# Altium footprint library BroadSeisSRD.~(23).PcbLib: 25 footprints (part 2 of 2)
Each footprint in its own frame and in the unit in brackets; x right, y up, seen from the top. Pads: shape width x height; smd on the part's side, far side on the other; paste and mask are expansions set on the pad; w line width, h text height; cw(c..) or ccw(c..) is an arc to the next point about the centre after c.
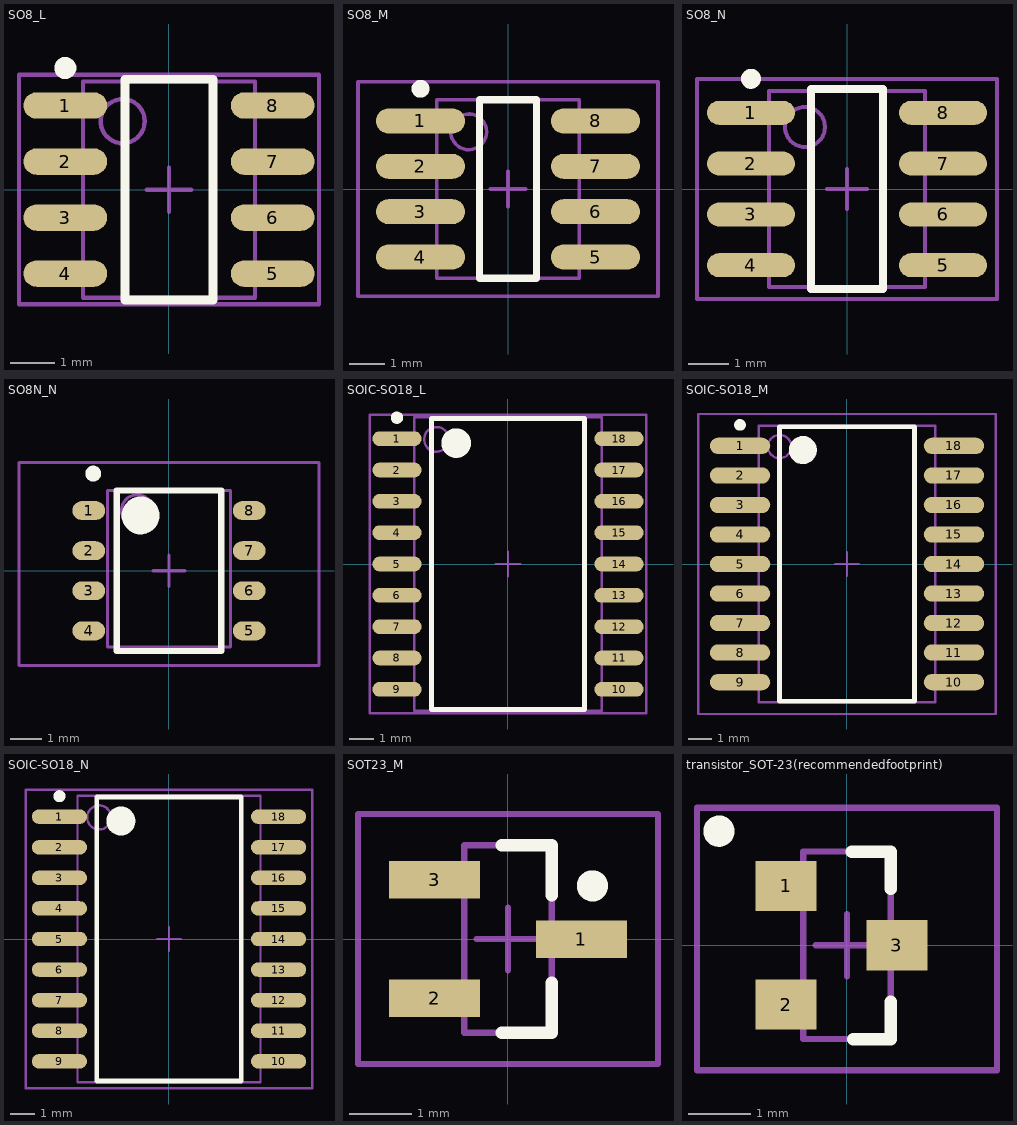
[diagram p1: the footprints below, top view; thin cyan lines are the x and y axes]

## SO8_L [mm] "SOIC, 8-Leads, Body 4.9x3.9mm, Pitch 1.27mm, IPC High Density"
height 1.75
pads (8):
  oval 1.9x0.6 smd: 1(-2.35,1.905) 2(-2.35,0.635) 3(-2.35,-0.635) 4(-2.35,-1.905) 5(2.35,-1.905) 6(2.35,-0.635) 7(2.35,0.635) 8(2.35,1.905)
Top Overlay:
  circle w0.25: c-2.35,2.755 r0.125
  lines w0.2: -1,-2.5 -1,2.5 1,2.5 1,-2.5 -1,-2.5
Mechanical 13:
  circle w0.1: c-1.05,1.55 r0.5
  lines w0.1: -1.95,-2.45 -1.95,2.45 1.95,2.45 1.95,-2.45 -1.95,-2.45
Mechanical 15:
  lines w0.1: -0.5,0 0.5,0 ; 0,-0.5 0,0.5 ; -3.4,-2.6 -3.4,2.6 3.4,2.6 3.4,-2.6 -3.4,-2.6
3D body: height 1.75, standoff 0, extent -1.95,-2.45 1.95,2.45

## SO8_M [mm] "SOIC, 8-Leads, Body 4.9x3.9mm, Pitch 1.27mm, IPC Low Density"
height 1.75
pads (8):
  oval 2.5x0.7 smd: 1(-2.45,1.905) 2(-2.45,0.635) 3(-2.45,-0.635) 4(-2.45,-1.905) 5(2.45,-1.905) 6(2.45,-0.635) 7(2.45,0.635) 8(2.45,1.905)
Top Overlay:
  circle w0.25: c-2.45,2.805 r0.125
  lines w0.2: -0.8,-2.5 -0.8,2.5 0.8,2.5 0.8,-2.5 -0.8,-2.5
Mechanical 13:
  circle w0.1: c-1.1,1.6 r0.5
  lines w0.1: -2,-2.5 -2,2.5 2,2.5 2,-2.5 -2,-2.5
Mechanical 15:
  lines w0.1: -0.5,0 0.5,0 ; 0,-0.5 0,0.5 ; -4.2,-3 -4.2,3 4.2,3 4.2,-3 -4.2,-3
3D body: height 1.75, standoff 0, extent -2,-2.5 2,2.5

## SO8_N [mm] "SOIC, 8-Leads, Body 4.9x3.9mm, Pitch 1.27mm, IPC Medium Density"
height 1.75
pads (8):
  oval 2.2x0.6 smd: 1(-2.4,1.905) 2(-2.4,0.635) 3(-2.4,-0.635) 4(-2.4,-1.905) 5(2.4,-1.905) 6(2.4,-0.635) 7(2.4,0.635) 8(2.4,1.905)
Top Overlay:
  circle w0.25: c-2.4,2.755 r0.125
  lines w0.2: -0.9,-2.5 -0.9,2.5 0.9,2.5 0.9,-2.5 -0.9,-2.5
Mechanical 13:
  circle w0.1: c-1.05,1.55 r0.5
  lines w0.1: -1.95,-2.45 -1.95,2.45 1.95,2.45 1.95,-2.45 -1.95,-2.45
Mechanical 15:
  lines w0.1: -0.5,0 0.5,0 ; 0,-0.5 0,0.5 ; -3.75,-2.75 -3.75,2.75 3.75,2.75 3.75,-2.75 -3.75,-2.75
3D body: height 1.75, standoff 0, extent -1.95,-2.45 1.95,2.45

## SO8N_N [mm] "SOP, 8-Leads, Body 5.3x5.3mm, Pitch 1.27mm, IPC Medium Density"
height 2.13
pads (8):
  oval 1.04x0.6 smd: 1(-2.54,1.905) 2(-2.54,0.635) 3(-2.54,-0.635) 4(-2.54,-1.905) 5(2.54,-1.905) 6(2.54,-0.635) 7(2.54,0.635) 8(2.54,1.905)
Top Overlay:
  circle w0.25: c-2.4,3.075 r0.125
  circle w0.6: c-0.9,1.75 r0.3
  lines w0.2: -1.651,-2.54 -1.651,2.54 1.651,2.54 1.651,-2.54 -1.651,-2.54
Mechanical 13:
  circle w0.1: c-1.008,1.905 r0.5
  lines w0.1: -1.95,-2.413 -1.95,2.54 1.95,2.54 1.95,-2.413 -1.95,-2.413
Mechanical 15:
  lines w0.1: -0.5,0 0.5,0 ; 0,-0.5 0,0.5 ; -4.75,-3 -4.75,3.425 4.75,3.425 4.75,-3 -4.75,-3
3D body: height 2.13, standoff 0, extent -2.286,-2.54 2.286,2.54

## SOIC-SO18_L [mm] "SOIC, 18-Leads, Body 11.5x7.5mm, Pitch 1.27mm, IPC High Density"
height 2.65
pads (18):
  oval 2x0.6 smd: 1(-4.5,5.08) 2(-4.5,3.81) 3(-4.5,2.54) 4(-4.5,1.27) 5(-4.5,0) 6(-4.5,-1.27) 7(-4.5,-2.54) 8(-4.5,-3.81) 9(-4.5,-5.08) 10(4.5,-5.08) 11(4.5,-3.81) 12(4.5,-2.54) 13(4.5,-1.27) 14(4.5,0) 15(4.5,1.27) 16(4.5,2.54) 17(4.5,3.81) 18(4.5,5.08)
Top Overlay:
  circle w0.25: c-4.5,5.93 r0.125
  circle w0.6: c-2.1,4.9 r0.3
  lines w0.2: -3.1,-5.9 -3.1,5.9 3.1,5.9 3.1,-5.9 -3.1,-5.9
Mechanical 13:
  circle w0.1: c-2.9,5.05 r0.5
  lines w0.1: -3.8,-5.95 -3.8,5.95 3.8,5.95 3.8,-5.95 -3.8,-5.95
Mechanical 15:
  lines w0.1: -0.5,0 0.5,0 ; 0,-0.5 0,0.5 ; -5.6,-6.05 -5.6,6.05 5.6,6.05 5.6,-6.05 -5.6,-6.05
3D body: height 2.65, standoff 0, extent -3.8,-5.95 3.8,5.95

## SOIC-SO18_M [mm] "SOIC, 18-Leads, Body 11.5x7.5mm, Pitch 1.27mm, IPC Low Density"
height 2.65
pads (18):
  oval 2.6x0.7 smd: 1(-4.6,5.08) 2(-4.6,3.81) 3(-4.6,2.54) 4(-4.6,1.27) 5(-4.6,0) 6(-4.6,-1.27) 7(-4.6,-2.54) 8(-4.6,-3.81) 9(-4.6,-5.08) 10(4.6,-5.08) 11(4.6,-3.81) 12(4.6,-2.54) 13(4.6,-1.27) 14(4.6,0) 15(4.6,1.27) 16(4.6,2.54) 17(4.6,3.81) 18(4.6,5.08)
Top Overlay:
  circle w0.6: c-1.9,4.9 r0.3
  circle w0.25: c-4.6,5.98 r0.125
  lines w0.2: -2.9,-5.9 2.9,-5.9 2.9,5.9 -2.9,5.9 -2.9,-5.9
Mechanical 13:
  circle w0.1: c-2.9,5.05 r0.5
  lines w0.1: -3.8,-5.95 3.8,-5.95 3.8,5.95 -3.8,5.95 -3.8,-5.95
Mechanical 15:
  lines w0.1: -0.5,0 0.5,0 ; 0,-0.5 0,0.5 ; -6.4,-6.45 6.4,-6.45 6.4,6.45 -6.4,6.45 -6.4,-6.45
3D body: height 2.65, standoff 0, extent -3.8,-5.95 3.8,5.95

## SOIC-SO18_N [mm] "SOIC, 18-Leads, Body 11.5x7.5mm, Pitch 1.27mm, IPC Medium Density"
height 2.65
pads (18):
  oval 2.3x0.6 smd: 1(-4.55,5.08) 2(-4.55,3.81) 3(-4.55,2.54) 4(-4.55,1.27) 5(-4.55,0) 6(-4.55,-1.27) 7(-4.55,-2.54) 8(-4.55,-3.81) 9(-4.55,-5.08) 10(4.55,-5.08) 11(4.55,-3.81) 12(4.55,-2.54) 13(4.55,-1.27) 14(4.55,0) 15(4.55,1.27) 16(4.55,2.54) 17(4.55,3.81) 18(4.55,5.08)
Top Overlay:
  circle w0.25: c-4.55,5.93 r0.125
  circle w0.6: c-2,4.9 r0.3
  lines w0.2: -3,-5.9 -3,5.9 3,5.9 3,-5.9 -3,-5.9
Mechanical 13:
  circle w0.1: c-2.9,5.05 r0.5
  lines w0.1: -3.8,-5.95 -3.8,5.95 3.8,5.95 3.8,-5.95 -3.8,-5.95
Mechanical 15:
  lines w0.1: -0.5,0 0.5,0 ; 0,-0.5 0,0.5 ; -5.95,-6.2 -5.95,6.2 5.95,6.2 5.95,-6.2 -5.95,-6.2
3D body: height 2.65, standoff 0, extent -3.8,-5.95 3.8,5.95

## SOT23_M [mm] "SOT23, 3-Leads, Body 2.9x1.3mm, Pitch 0.95mm, Lead Span 2.3mm - Reverse Pinning, IPC Low Density"
height 1.1
pads (3):
  rect 1.45x0.6 smd: 1(1.175,0) 2(-1.175,-0.95) 3(-1.175,0.95)
Top Overlay:
  circle w0.25: c1.35,0.85 r0.125
  lines w0.2: -0.1,-1.5 0.7,-1.5 0.7,-0.7 ; -0.1,1.5 0.7,1.5 0.7,0.7
Mechanical 13:
  lines w0.1: -0.7,-1.5 -0.7,1.5 0.7,1.5 0.7,-1.5 -0.7,-1.5
Mechanical 15:
  lines w0.1: -0.5,0 0.5,0 ; 0,-0.5 0,0.5 ; -2.4,-2 -2.4,2 2.4,2 2.4,-2 -2.4,-2
3D body: height 1.1, standoff 0, extent -0.7,-1.5 0.7,1.5

## transistor_SOT-23(recommendedfootprint) [mm] "SOT23, 3-Leads, Body 2.9x1.3mm, Pitch 0.95mm, Lead Span 2.5mm, IPC Low Density"
height 1.1
pads (3):
  rect 0.972x0.802 smd: 1(-0.975,0.95) 2(-0.975,-0.95) 3(0.8,0)
Top Overlay:
  circle w0.25: c-2.05,1.825 r0.125
  lines w0.2: 0.075,1.5 0.7,1.5 0.7,0.9 ; 0.1,-1.5 0.7,-1.5 0.7,-0.9
Mechanical 13:
  lines w0.1: -0.7,-1.5 -0.7,1.5 0.7,1.5 0.7,-1.5 -0.7,-1.5
Mechanical 15:
  lines w0.1: -0.5,0 0.5,0 ; 0,-0.5 0,0.5 ; -2.4,-2 -2.4,2.2 2.4,2.2 2.4,-2 -2.4,-2
3D body: height 1.1, standoff 0, extent -0.7,-1.5 0.7,1.5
